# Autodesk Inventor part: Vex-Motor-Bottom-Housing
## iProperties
Created: 2007-08
Part Number: Vex-Motor-Bottom-Housing
Material: ABS Plastic
Document SubType Name: Modeling
Density: 1.06 g/cm^3
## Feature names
1. Base1
